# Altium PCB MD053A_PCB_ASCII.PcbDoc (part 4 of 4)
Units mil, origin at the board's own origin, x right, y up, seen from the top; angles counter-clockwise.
Board outline 3650 x 5180 mil, 4 copper layers (Top Layer, GND Layer, Power Layer, Bottom Layer), stack 58.4 mil thick; 251 components, 138 nets, 532 pads, 1017 vias.
Unrouted connection lines stored in the file: 42.
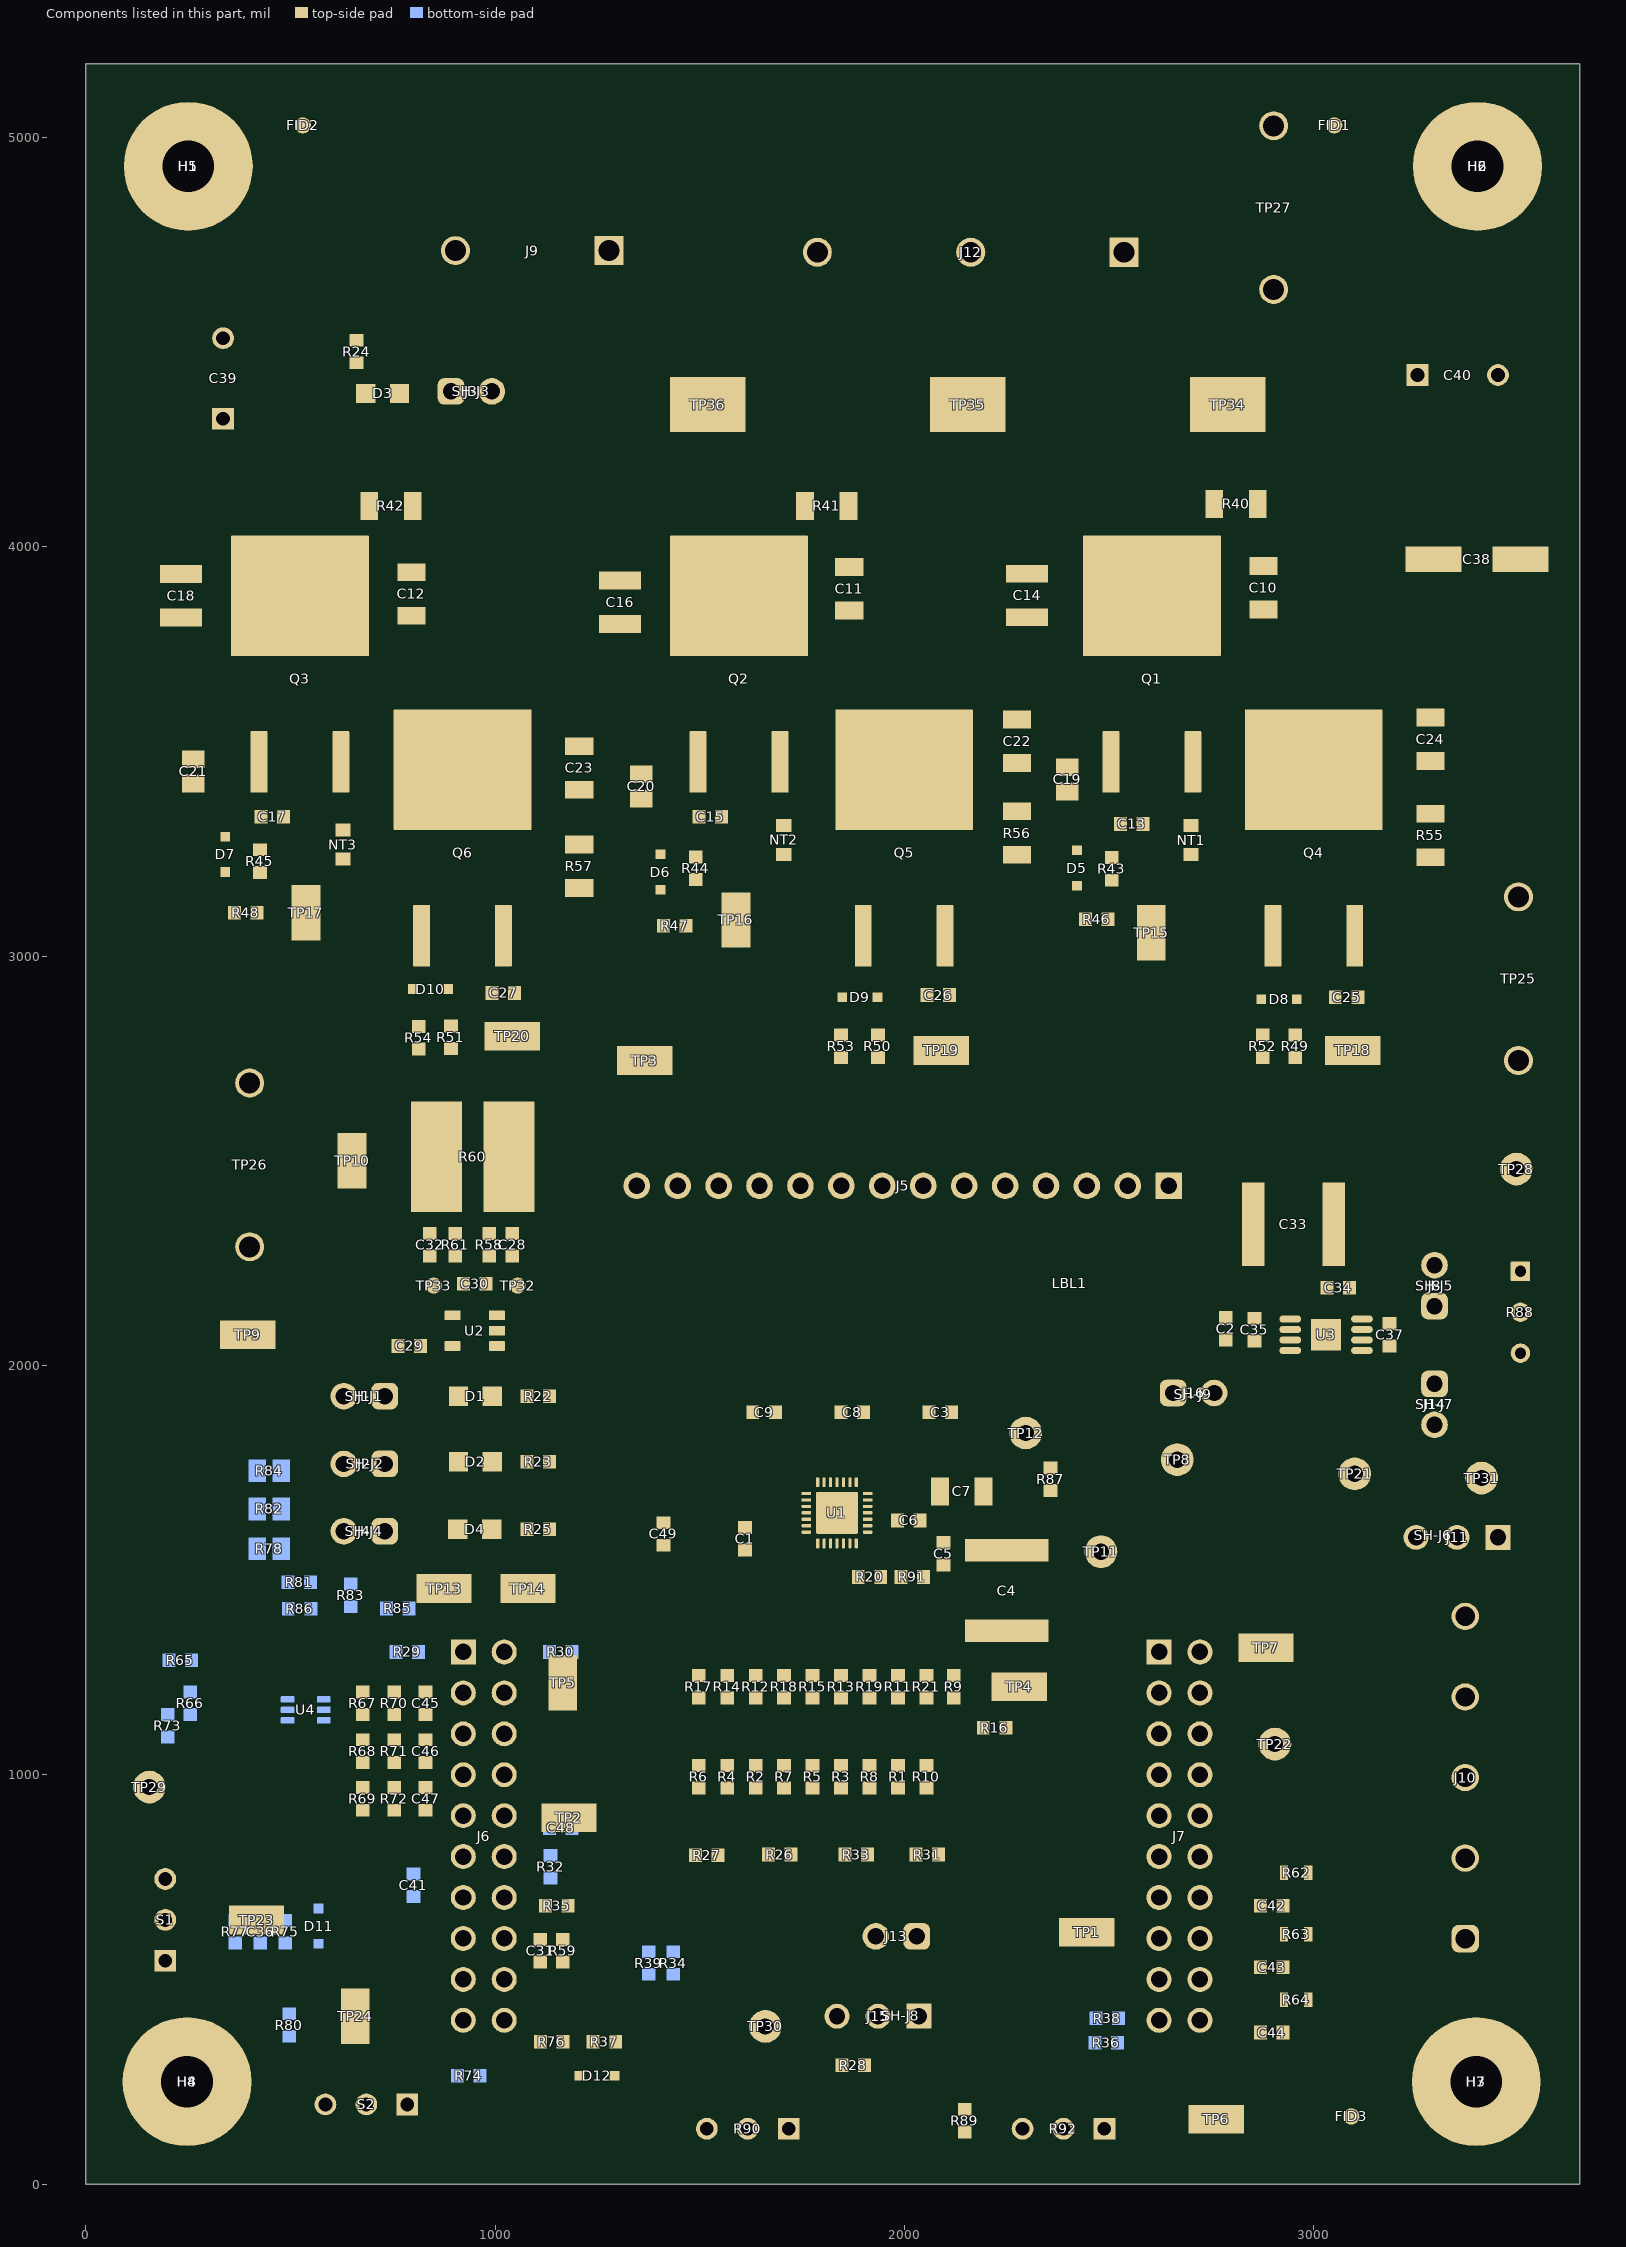
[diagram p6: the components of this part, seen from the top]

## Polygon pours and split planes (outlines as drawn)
GVDD on Top Layer "TOP_LAYER_GVDD_P124" (solid, remove dead copper, pour order 124): 2079.4,1760.22 2111.75,1760.22 2246.54,1895 2375,1895 2375,1726.8 2373.2,1725 2369.08,1729.12 2140,1729.12 2140,1655.75 1962.16,1648.98
PVDD on Top Layer "TOP_LAYER_PVDD_P128" (solid, remove dead copper, pour order 128): 3005,2515 3005,2225 3057.17,2225 3057.17,2125 3080,2125 3080,2102.56 3150,2102.56 3150,2190 3345,2190 3345,2515
GND on Top Layer "TOP_LAYER_GND_P157" (solid, remove dead copper, pour order 157): 24.84,5196.95 3674.84,5196.95 3674.84,16.95 24.84,16.95
AVDD on Top Layer "TOP_LAYER_AVDD_P145" (solid, remove dead copper, pour order 145): 1701.22,1905 1365,1905 1342.2,1882.2 1342.2,1777.53 1354.73,1765 1605.25,1765 1605.25,1830.55 1683.62,1830.55 1725.32,1872.25 1701.22,1896.35
PVDD on Top Layer "TOP_LAYER_PVDD_P144" (solid, remove dead copper, pour order 144): 2890,4565 3356.77,4565 3375,4546.77 3375,3690.23 3345,3680.72 3150,3680.72 3150,4170 2890,4430
LSS on Top Layer "TOP_LAYER_LSS_P141" (solid, remove dead copper, pour order 141): 930,3430 3331.96,3430 3405,3356.96 3405,3171.26 3310,3076.26 3310,2477.55 1412.92,2477.55 1395.1,2355 1284,2355 1240,2355 1110,2355 1090,2375 970,2375 970,2920.47 680.94,3135 680,3244.68 970,3361.8
GLA_FET on Top Layer "TOP_LAYER_GLA_FET_P139" (solid, remove dead copper, pour order 139): 2875,3130 2922.73,3130 2927.73,3125 2935.94,2950 3060.5,2940 3080,2920.5 3080,2780 2920,2780 2915,2785 2915,2919.83 2875,2959.83
GLB_FET on Top Layer "TOP_LAYER_GLB_FET_P138" (solid, remove dead copper, pour order 138): 1868.41,3132.12 1919.81,3132.12 1926.42,3125.51 1926.42,2981.32 1975.47,2932.27 2078.23,2932.27 2085,2925.5 2085,2775 2065,2755 2040,2780 1890,2780 1890,2950 1868.31,2950
GLC_FET on Top Layer "TOP_LAYER_GLC_FET_P137" (solid, remove dead copper, pour order 137): 790,3133.59 791.47,3132.12 855,3132.12 855,2990 907.42,2937.58 1024.72,2937.58 1024.72,2870.28 1067.44,2827.56 1068.11,2740 979.89,2740 850,2740 850,2915.33 815,2950.33 790,2950.33
GHA_FET on Top Layer "TOP_LAYER_GHA_FET_P136" (solid, remove dead copper, pour order 136): 2445,3561.47 2575,3561.47 2575,3377.97 2555,3357.97 2555,3251.8 2635,3171.8 2635,3035 2564.4,3035 2564.4,3168.55 2522.95,3210 2409.59,3210 2409.59,3296.92 2445,3332.33
GHB_FET on Top Layer "TOP_LAYER_GHB_FET_P135" (solid, remove dead copper, pour order 135): 1445,3563.13 1447.66,3565.78 1565,3565.78 1565,3385 1522.44,3385 1525,3382.44 1525,3284.98 1625,3184.98 1625,3052.68 1617.32,3045 1533.11,3045 1530,3048.11 1530,3216.78 1526.78,3220 1380,3220 1380,3282.42 1445,3347.42
GHC_FET on Top Layer "TOP_LAYER_GHC_FET_P134" (solid, remove dead copper, pour order 134): 350,3565.78 350,3361.95 323.38,3335.33 323.38,3237.91 459.69,3237.91 467.6,3230 467.6,3080.51 500,3048.11 572.34,3048.11 572.34,3224.36 457.72,3338.98 457.72,3565.78
GND on Top Layer "TOP_LAYER_GND_P133" (solid, remove dead copper, pour order 133): 1169,3904.41 1434.08,3904.41 1437.58,3900.91 1437.58,3575.12 1173.88,3575.12 1169,3580
GND on Top Layer "TOP_LAYER_GND_P132" (solid, remove dead copper, pour order 132): 2184.35,3914.49 2443.8,3914.49 2462.2,3896.09 2462.2,3619.49 2459.53,3622.17 2184.35,3622.17
PVDD on Top Layer "TOP_LAYER_PVDD_P131" (solid, remove dead copper, pour order 131): 2803.49,3682.2 2803.49,4136.78 2725.26,4215 2291.73,4215 2291.73,4103.85 2244.09,4056.21 2235,4056.21 2235,3919.41 2250,3904.41 2422.56,3904.41 2435.08,3891.89 2435.08,3622.17 2350,3537.09 2350,3446.49 2360.98,3435.51 2437.68,3435.51 2450,3447.83 2450,3537.09 2564.4,3580 2592.91,3680 2602.4,3680
PVDD on Top Layer "TOP_LAYER_PVDD_P130" (solid, remove dead copper, pour order 130): 1775.57,3655 1775.57,4023.9 1806.68,4055 1803.68,4058 1801.38,4058 1801.38,4132.76 1848.62,4180 1893.74,4180 1892.29,4215 1489.15,4215 1341.24,4055 1287.6,4055 1225,3992.4 1225,3880.2 1400.43,3880.2 1411.06,3869.57 1411.06,3665.2 1411.06,3647.14 1382.58,3574.19 1300,3517.09 1300,3411.65 1421.26,3415.15 1559.71,3655
PVDD on Top Layer "TOP_LAYER_PVDD_P129" (solid, remove dead copper, pour order 129): 710.13,4006.54 747.36,4043.77 747.36,4170.44 1015.44,4170.44 1450,4605 1450,4842.44 1412.44,4880 1174.2,4880 1124.2,4830 1124.2,4829.2 1100,4805 1100,4700 855,4455 611,4455 561,4426.57 539.43,4426.57 301.85,4426.57 150.67,4275.39 150.67,3905 313.11,3905 313.11,3652.43 207.48,3585.59 207.48,3467.91 325.15,3467.91 653.18,3652.43 710.13,3709.38
OUTA on Top Layer "TOP_LAYER_OUTA_P127" (solid, remove dead copper, pour order 127): 2762.91,3283.5 2560,3283.5 2560,3376.97 2602.4,3419.37 2602.4,3645.17 2612.46,3655.23 2816.93,3655.23 2816.93,3891.89 2830.04,3905 2917.56,3905 2917.56,4145.16 2882.72,4180 2787.91,4180 2758.75,4218.66 2626.5,4218.66 2381.1,4489.1 2381.1,4880 2656.8,4880 2760.94,4775.85 2760.94,4614.69 3175,4200.63 3175,3682.2 3224.2,3633 3375,3633 3375,3555 3350,3530 3199.98,3530 3199.98,3234.88 3170.1,3205 2762.91,3205
OUTB on Top Layer "TOP_LAYER_OUTB_P126" (solid, remove dead copper, pour order 126): 1550,3292.2 1535,3292.2 1535,3367.94 1556.8,3377.42 1556.8,3619.49 1806.68,3619.49 1806.68,3878.8 1832.87,3905 1929.13,3905 1890.66,4230.2 1680,4230.2 1899.05,4455 1982.81,4538.76 1988.23,4880 2315,4880 2365,4880 2365,4488.16 2615.89,4220 2319.31,4220 2315,4156.04 2211.32,4052.36 2211.32,3649.5 2325,3649.5 2322.64,3647.14 2322.64,3519.49 2201.02,3519.49 2201.02,3263.6 2156.8,3219.37 1778.58,3219.37 1778.58,3283.5 1769.88,3292.2 1561.52,3292.2 1556.8,3292.2
OUTC on Top Layer "TOP_LAYER_OUTC_P125" (solid, remove dead copper, pour order 125): 465.1,3540.65 579.45,3655 747.36,3655 747.36,3869.57 736.93,3880 868.48,3880.2 868.48,4155 1006.9,4161.5 1745.5,4880 1960.31,4880 1964.76,4634.76 1964.76,4505 1690,4229.32 1575,4229.32 1410,4080 1275,4080 1200,4005 1200,3630 1265.99,3564.01 1265.99,3467.91 1137.91,3467.91 1121.97,3451.97 1121.97,3255 703.72,3255 683.31,3275.42 519.33,3275.42 465.1,3329.65
LSS on Power Layer "POWER_LAYER_LSS_P140" (solid, remove dead copper, pour order 140): 930,3430 3331.96,3430 3405,3356.96 3405,3171.26 3310,3076.26 3310,2477.55 1412.92,2477.55 1395.1,2355 1284,2355 1240,2355 1110,2355 1090,2375 970,2375 970,2920.47 680.94,3135 680,3244.68 970,3361.8
GND on Power Layer "POWER_LAYER_GND_P165" (solid, remove dead copper, pour order 165): 0,5180 3650,5180 3650,0 0,0
AVDD on Power Layer "POWER_LAYER_AVDD_P153" (solid, remove dead copper, pour order 153): 1702.02,1904.76 1365.8,1904.76 1343,1881.96 1343,1777.29 1355.53,1764.76 1565,1764.76 1635,1830.31 1684.42,1830.31 1726.12,1872.01 1702.02,1896.11
PVDD on Power Layer "POWER_LAYER_PVDD_P149" (solid, remove dead copper, pour order 149): 1412.44,4880 1450,4842.44 1450,4628.1 1051.9,4230 3192,4230 2890,4521.68 2890,4565 3385.61,4565 3387.09,4563.52 3386,4218 3386,3275.5 3277.16,3166.66 416.21,3166.66 313.11,3269.76 313.11,3905 150.67,3905 150.67,4275.39 301.85,4426.57 561,4426.57 589.42,4455 855,4455 1100,4700 1100,4805.8 1174.2,4880
OUTA on Power Layer "POWER_LAYER_OUTA_P148" (solid, remove dead copper, pour order 148): 3174.36,4185 2786.28,4185 2757.11,4223.66 2624.86,4223.66 2379.47,4494.1 2379.47,4885 2655.16,4885 2759.31,4780.85 2759.31,4619.69 3174.36,4227.33
OUTB on Power Layer "POWER_LAYER_OUTB_P147" (solid, remove dead copper, pour order 147): 2319,4230.2 1680,4230.2 1899.05,4455 1982.81,4538.76 1988.23,4880 2315,4880 2365,4880 2365,4488.16 2604,4230.2
OUTC on Power Layer "POWER_LAYER_OUTC_P146" (solid, remove dead copper, pour order 146): 1077.62,4231.84 1746.12,4881.84 1965.38,4880 1965.38,4636.6 1965.38,4506.84 1690.62,4231.16
LSS on GND Layer "GND_LAYER_LSS_P158" (solid, remove dead copper, pour order 158): 930,3430 3331.96,3430 3405,3356.96 3405,3171.26 3310,3076.26 3310,2477.55 1412.92,2477.55 1395.1,2355 1284,2355 1240,2355 1110,2355 1090,2375 970,2375 970,2920.47 680.94,3135 680,3244.68 970,3361.8
GND on GND Layer "GND_LAYER_GND_P159" (solid, remove dead copper, pour order 159): 0,5180 3650,5180 3650,0 0,0
OUTA on GND Layer "GND_LAYER_OUTA_P152" (solid, remove dead copper, pour order 152): 3208.31,4184.48 2800.59,4184.48 2771.43,4223.14 2639.17,4223.14 2393.78,4493.58 2393.78,4884.48 2669.47,4884.48 2773.62,4780.33 2773.62,4619.17
OUTB on GND Layer "GND_LAYER_OUTB_P151" (solid, remove dead copper, pour order 151): 2319,4230.2 1680,4230.2 1899.05,4455 1982.81,4538.76 1988.23,4880 2315,4880 2365,4880 2365,4488.16 2604,4230.2
OUTC on GND Layer "GND_LAYER_OUTC_P150" (solid, remove dead copper, pour order 150): 1081.11,4231.82 1749.61,4881.82 1968.87,4879.99 1968.87,4636.59 1968.87,4506.82 1694.11,4231.15
LSS on Bottom Layer "BOTTOM_LAYER_LSS_P143" (solid, remove dead copper, pour order 143): 930,3430 3331.96,3430 3405,3356.96 3405,3171.26 3310,3076.26 3310,2477.55 1412.92,2477.55 1395.1,2355 1284,2355 1240,2355 1110,2355 1090,2375 970,2375 970,2920.47 680.94,3135 680,3244.68 970,3361.8
OUTA on Bottom Layer "BOTTOM_LAYER_OUTA_P156" (solid, remove dead copper, pour order 156): 3208.31,4180 2800.59,4180 2771.43,4218.66 2639.17,4218.66 2393.78,4489.1 2393.78,4880 2669.47,4880 2773.62,4775.85 2773.62,4614.69
OUTB on Bottom Layer "BOTTOM_LAYER_OUTB_P155" (solid, remove dead copper, pour order 155): 2325,4225 1686,4225 1905.06,4449.8 1988.81,4533.55 1994.23,4874.8 2321,4874.8 2371,4874.8 2371,4482.95 2610,4225
OUTC on Bottom Layer "BOTTOM_LAYER_OUTC_P154" (solid, remove dead copper, pour order 154): 1081.11,4231.82 1749.61,4881.82 1968.87,4879.99 1968.87,4636.59 1968.87,4506.82 1694.11,4231.15
GND on Bottom Layer "BOTTOM_LAYER_GND_P167" (solid, remove dead copper, pour order 167): 0,5180 3650,5180 3650,0 0,0

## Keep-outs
Keep-Out Layer:
  text ".Layer_Name" at 577,-428.49 h60

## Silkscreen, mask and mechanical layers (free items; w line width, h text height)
Top Overlay:
  lines w8: 314,776 330,792 ; 316,472 334,454 ; 330,733 330,792 ; 334,513 334,454 ; 346,776 330,792 ; 351,471 334,454 ; 515,380 495,360 ; 516,339 495,360 ; 571,360 495,360 ; 747,369 819,369 800,388 ; 800,352 818,370
  lines w10: 1462.65,1060 2090,1060 2090,1270 ; 2204,1596 2205,1595 ; 2204,1596 2205,1595 ; 2204,1596 2204,1925 1570,1925 1570,1456.48 2120.5,1456.48 2120.5,1310 2371.66,1310 2371.66,1595 2355,1595 2205,1595 ; 1462.65,850 1462.65,1270 2155,1270 2155,850 1462.65,850
  text "GND" at 833.69,4455 h40
  text "PVDD" at 1200,4455 h40
  text "OUTC" at 1711.59,4454.45 h40
  text "OUTB" at 2084.79,4454.45 h40
  text "OUTA" at 2458,4454.45 h40
  text "LSS" at 1344.97,2511.91 h30 r45
  text "GLC" at 1438.97,2509.91 h30 r45
  text "SHC" at 1638.97,2506.91 h30 r45
  text "GHC" at 1536.97,2503.91 h30 r45
  text "BSTC" at 1744.97,2503.91 h30 r45
  text "GLB" at 1857.97,2503.91 h30 r45
  text "GHB" at 1952.97,2503.91 h30 r45
  text "SHB" at 2053.97,2503.91 h30 r45
  text "BSTB" at 2149.97,2503.91 h30 r45
  text "GLA" at 2258.97,2503.91 h30 r45
  text "GHA" at 2368.97,2503.91 h30 r45
  text "SHA" at 2469.97,2503.91 h30 r45
  text "BSTA" at 2562.97,2503.91 h30 r45
  text "GND" at 2669.97,2503.91 h30 r45
  text "LDO_" at 3235,2365 h30
  text "EN" at 3256.86,2320 h30
  text "DRV8328A/B/C/D" at 1648.36,1945 h35
  text "AVDD" at 445,1889.57 h30
  text "DT" at 3479.33,1875.99 h30
  text "DT_POT" at 3042.76,1870 h30
  text "EXT_" at 3475,1765 h30
  text "HALL_" at 3175,1735 h30
  text "nFAULT" at 382.01,1726 h30
  text "HALL_" at 3475,1720 h30
  text "PWR" at 3175,1695 h30
  text "PWR" at 3475,1677.56 h30
  text "HALL_PWR_" at 2829.03,1605 h30
  text "MCU_LED" at 342.73,1560.1 h30
  text "SEL" at 3010,1545 h30
  text "EXT" at 3560,1540 h30 r90
  text "AVDD" at 3172.2,1525 h30 r90
  text "AVDD cap" at 1311.03,1496.81 h25
  text "(for C/D)" at 1308.48,1457.2 h25
  text "HALL" at 2997.79,1420 h35
  text "A/B" at 1874.37,1415 h30
  text "DT" at 1993.06,1370 h30
  text "PWR" at 3032.2,1365 h35
  text "HALLA" at 2961.09,1180 h35
  text "DRV8328AEVM" at 173.27,1121.81 h120 r90
  text "A/B" at 1435,1120 h30 r90
  text "'.PRJ_Number'.PCB_Rev" at 291.7,1111.24 h108.27 r90
  text "HALLB" at 2966.09,977.2 h35
  text "C/D" at 1430,920 h30 r90
  text "HALLC" at 2966.54,796.3 h35
  text "SLEEP" at 396.2,735 h30 r90
  text "VDS_DIS" at 1879.36,673.51 h30
  text "GND" at 3030.31,535 h35
  text "DRV" at 733,442 h30
  text "DRV" at 497,440 h30
  text "WAKE" at 403.97,430 h30 r90
  text "VDS_EXT" at 1395,400.99 h30
  text "OFF" at 496,396 h30
  text "ON" at 734,396 h30
  text "POT" at 2143.46,370.67 h30 r90
  text "EXT" at 1764.15,367.64 h30 r90
  text "VDSLVL" at 2302.65,255.57 h30
  text ".Layer_Name" at 577,-428.49 h60
Bottom Overlay:
  text ".Layer_Name" at 577,-428.49 h60
Top Paste:
  text ".Layer_Name" at 577,-428.49 h60
Bottom Paste:
  text ".Layer_Name" at 577,-428.49 h60
Top Solder:
  text ".Layer_Name" at 577,-428.49 h60
  text ".Layer_Name" at 577,-428.49 h60
Solder Side:
  text ".Layer_Name" at 577,-428.49 h60
Drill Guide:
  text ".Layer_Name" at 577,-428.49 h60
M1 Board Outline:
  the board outline again, w10
  text ".Layer_Name" at 577,-428.49 h60
M2 Board Dimensions:
  rectangle: 0,155 125,280
  rectangle: 125,30 500,155
  lines w7: 0,155 1000,155 ; 125,30 125,280 ; 250,30 250,280 ; 500,30 500,280 ; 750,30 750,280 ; 0,30 1000,30 1000,280 0,280 0,30
  text ".Layer_Name" at 577,-428.49 h60
M3 3D STEP Top:
  text ".Layer_Name" at 577,-428.49 h60
M4 3D STEP Bottom:
  text ".Layer_Name" at 577,-428.49 h60
M5 Assembly Top:
  lines w10: -292,-500.17 6308,-500.17 ; -292,-296.83 6310,-296.83 ; -292,-93.5 -292,-703.5 3713,-703.5 6310,-703.5 6310,-93.5 -291.5,-93.5 -291.5,-703.5 1284,-703.5 ; 2173,-703.5 2173,-93.5 ; 3440,-296.83 3440,-93.5 ; 4280,-296.83 4280,-93.5 ; 4902,-710 4902,-507.17
  text "COMPONENTS MARKED 'DNP' SHOULD NOT BE POPULATED." at 1153.5,111.5 h60
  text "ASSEMBLY VARIANT:" at 1153,-4 h60
  text ".VariantName" at 2189,-4 h60
  text "PCB VIEWED FROM TOP SIDE" at -228.5,-225.67 h60
  text "BOARD #:" at 2248,-225.67 h60
  text ".PRJ_Number" at 2793.5,-225.67 h60
  text "REV:" at 3638,-225.67 h60
  text ".PCB_Rev" at 3929.5,-225.67 h60
  text "SVN REV:" at 4476,-225.67 h60
  text ".VersionControl_RevNumber" at 4982,-225.67 h60
  text "TID #:" at 2248,-429 h60
  text ".TID" at 2793.5,-429 h60
  text "PLOT NAME =" at -228.5,-634.34 h60
  text ".plot_File_Name" at 577,-634.34 h60
  text "GENERATED    :" at 2250,-634.34 h60
  text ".Print_Date" at 3119.5,-634.34 h60
  text ".Print_Time" at 3848.5,-634.34 h60
  text "TEXAS INSTRUMENTS" at 5113,-634.34 h60
M6 Assembly Bottom:
  lines w10: -292.5,-297.33 6309.5,-297.33 ; -290.5,-500.67 6309.5,-500.67 ; 1115.5,-710.5 1115.5,-507.67 ; 1737.5,-297.33 1737.5,-94 ; 2577.5,-297.33 2577.5,-94 ; 3844.5,-704 3844.5,-94 ; 4733.5,-704 6309,-704 6309,-94 -292.5,-94 -292.5,-704 2304.5,-704 6309.5,-704 6309.5,-94
  text "COMPONENTS MARKED 'DNP' SHOULD NOT BE POPULATED." at 6102,112 h60
  text ".VariantName" at 5058,-4 h60
  text "ASSEMBLY VARIANT:" at 6097,-4 h60
  text ".VersionControl_RevNumber" at 1035.5,-226.17 h60
  text "SVN REV:" at 1541.5,-226.17 h60
  text ".PCB_Rev" at 2088,-226.17 h60
  text "REV:" at 2379.5,-226.17 h60
  text ".PRJ_Number" at 3224,-226.17 h60
  text "BOARD #:" at 3769.5,-226.17 h60
  text "PCB VIEWED FROM BOTTOM SIDE" at 6246,-226.17 h60
  text ".TID" at 3224,-429.5 h60
  text "TID #:" at 3769.5,-429.5 h60
  text "TEXAS INSTRUMENTS" at 904.5,-634.84 h60
  text ".Print_Time" at 2169,-634.84 h60
  text ".Print_Date" at 2898,-634.84 h60
  text "GENERATED    :" at 3767.5,-634.84 h60
  text ".plot_File_Name" at 5440.5,-634.84 h60
  text "PLOT NAME =" at 6246,-634.84 h60
M9 Title Sheet:
  lines w10: -491.5,1471.5 -291.5,1471.5 ; -491.5,3846.5 -291.5,3846.5 ; -491.5,6221.5 -291.5,6221.5 ; 2008.5,-903.5 2008.5,-703.5 ; 2008.5,8396.5 2008.5,8596.5 ; 4508.5,-903.5 4508.5,-703.5 ; 4508.5,8396.5 4508.5,8596.5 ; 6321,-703.5 6321,-93.5 11303.5,-93.5 ; 7008.5,-903.5 7008.5,-703.5 ; 7008.5,8396.5 7008.5,8596.5 ; 9508.5,-903.5 9508.5,-703.5 ; 9508.5,8396.5 9508.5,8596.5 ; 11303.5,-703.5 11303.5,-93.5 ; 11303.5,-393.5 14303.5,-393.5 ; 11303.5,206.5 14303.5,206.5 ; 11304.5,800.5 14304.5,800.5 ; 12008.5,-903.5 12008.5,-703.5 ; 12008.5,8396.5 12008.5,8596.5 ; 12808.5,-693.5 12808.5,-93.5 ; 14303.5,-93.5 11303.5,-93.5 ; 14303.5,506.5 11303.5,506.5 ; 14308.5,496.5 14308.5,-703.5 ; 14308.5,1301 11304.5,1301 11303.5,1301 11303.5,800.5 11303.5,506.5 ; 14308.5,1471.5 14508.5,1471.5 ; 14308.5,3846.5 14508.5,3846.5 ; 14308.5,6221.5 14508.5,6221.5 ; 11303.5,-93.5 11303.5,506.5 ; 14308.5,-703.5 14308.5,8396.5 -291.5,8396.5 -291.5,-703.5 14308.5,-703.5 ; -491.5,-903.5 -491.5,8596.5 14508.5,8596.5 14508.5,-903.5 -491.5,-903.5
  text "1" at 739.84,8466.5 h70
  text "2" at 3235.5,8466.5 h70
  text "3" at 5724.84,8466.5 h70
  text "4" at 8231.51,8466.5 h70
  text "5" at 10730.5,8466.5 h70
  text "6" at 13235.5,8466.5 h70
  text "A" at -416.5,7323.5 h70
  text "A" at 14383.5,7323.5 h70
  text "B" at -416.5,4943.5 h70
  text "B" at 14383.5,4943.5 h70
  text "C" at -416.5,2568.5 h70
  text "C" at 14383.5,2568.5 h70
  text "PROJECT TITLE:" at 11343.5,707.5 h45
  text ".PRJ_Title" at 11393.5,574.17 h70
  text "DESIGNED FOR:" at 11343.5,406.5 h45
  text ".PRJ_Customer" at 11393.5,266.5 h70
  text "D" at -416.5,198.5 h70
  text "D" at 14383.5,198.5 h70
  text "FILE NAME:" at 11343.5,106.5 h45
  text ".PCB_File_Name_No_Path" at 11393.5,-13.5 h70
  text "Texas Instruments (TI) and/or its licensors do not warrant the accuracy or completeness of this specification" at 6374,-175.34 h45
  text "ENGINEER:" at 11343.5,-183.5 h45
  text "LAYOUT BY:" at 12848.5,-183.5 h45
  text "or any information contained therein. TI and/or its licensors do not warrant that this design will meet" at 6329.01,-288 h45
  text ".PRJ_Engineer" at 11393.5,-338.49 h70
  text ".PCB_Layout" at 12899,-338.49 h70
  text "the specifications, will be suitable for your application or fit for any particular purpose, or will operate in" at 6329.01,-400.67 h45
  text ".Layer_Name" at 577,-428.49 h60
  text "ALTIUM DESIGNER VERSION:" at 12848.5,-493.5 h45
  text "an implementation. TI and/or its licensors do not warrant that the design is production worthy. You should" at 6329.01,-513.33 h45
  text "completely validate and test your design implementation to confirm the system functionality for your application." at 6374,-626 h45
  text ".print_Scale" at 11393.5,-626.83 h70
  text ".Application_BuildNumber" at 12899,-626.83 h70
  text "1" at 739.84,-833.5 h70
  text "2" at 3235.5,-833.5 h70
  text "3" at 5724.84,-833.5 h70
  text "4" at 8231.51,-833.5 h70
  text "5" at 10730.5,-833.5 h70
  text "6" at 13235.5,-833.5 h70
M10 Fab Notes:
  drawing of 189 lines, arcs and shapes, not listed
  text "DESIGN INFORMATION" at 12382.02,6786.17 h60
  text "MIN. TRACK WIDTH:" at 11737.46,6654.05 h60
  text "8" at 12833.7,6654.05 h60
  text "MIL" at 12988.46,6654.05 h60
  text "MIN. CLEARANCE:" at 11737.46,6529.92 h60
  text "0.2" at 12773.7,6529.93 h60
  text "mm" at 12988.46,6529.92 h60
  text "MIN. VIA PAD SIZE:" at 11737.46,6405.8 h60
  text "24" at 12803.71,6405.8 h60
  text "MIL" at 12988.46,6405.8 h60
  text "0.05mm (2MIL)" at 12432.46,6275.9 h60
  text "MINIMUM ANNULAR RING" at 11408.23,6267.67 h60
  text "EXTERNAL" at 13140.46,6267.67 h60
  text "PER" at 11608.23,6157.55 h60
  text "IPC-D-275 CLASS 2 LEVEL C" at 11828.23,6157.54 h60
  text "MIL, HOLES" at 13316.46,6057.07 h60
  text "+/-" at 12924,6048.48 h60
  text "+/-" at 13778,6048.48 h60
  text "REGISTRATION TOLERANCES:" at 11408.23,6047.42 h60
  text "METAL" at 12608,6047.42 h60
  text "5" at 13184.2,6047.42 h60
  text "3" at 14017.2,6047.42 h60
  text "MIL" at 14133.46,6047.42 h60
  text "HOLE SIZE TOLERANCE (UNLESS OTHERWISE SPECIFIED):" at 11408.23,5949.1 h60
  text "+/-" at 13778,5946.23 h60
  text "3" at 14017.2,5945.17 h60
  text "MIL" at 14133.46,5945.17 h60
  text "MATERIAL:" at 11333.46,5807.52 h60
  text "FR-4 High Tg" at 12319.9,5679 h60
  text "X" at 12175.46,5671.01 h60
  text "FR-408" at 11754.46,5666.49 h60
  text "OTHER" at 13242.46,5666.49 h60
  text "62 MIL (1.6mm) +/-10%" at 12074.56,5523.46 h60
  text "X" at 11954.46,5521.01 h60
  text "THICKNESS:" at 11408.23,5515.24 h60
  text "OTHER" at 13359.46,5515.24 h60
  text "TOLERANCE:" at 11408.23,5376.92 h60
  text "X" at 12256.46,5376.92 h60
  text "ANSI IPC-6012 TYPE 3 CLASS 2" at 12434.48,5376.92 h60
  text "OTHER +/-" at 12434.46,5232.73 h60
  text "BOW & TWIST:" at 11408.23,5087.54 h60
  text "X" at 12256.46,5087.54 h60
  text "ANSI IPC-6012 TYPE 3 CLASS 2" at 12434.48,5087.54 h60
  text "OTHER +/-" at 12434.46,4940.85 h60
  text "DRILLING:" at 11333.46,4810.23 h60
  text "NC_DRILL FILES" at 13094.46,4705.04 h60
  text "REFERENCE:" at 11408.23,4701.1 h60
  text "X" at 12065.46,4701.01 h60
  text "AS SHOWN" at 12243.46,4701.1 h60
  text "X" at 12966.46,4701.1 h60
  text "OTHER" at 13392.46,4558.85 h60
  text "PTH COPPER THICKNESS:" at 11407.91,4555.32 h60
  text "X" at 12547.14,4555.32 h60
  text "20-30 um" at 12675.14,4555.32 h60
  text "BOARD FINISH:" at 11333.46,4407.73 h60
  text "SILKSCREEN:" at 11488.68,4297.6 h60
  text "X" at 12446.46,4297.6 h60
  text "TOP" at 12563.46,4297.6 h60
  text "X" at 12956.46,4297.6 h60
  text "BOTTOM" at 13074.46,4297.6 h60
  text "SILKSCREEN COLOR:" at 11488.68,4142.41 h60
  text "X" at 12445.46,4142.41 h60
  text "WHITE" at 12563.46,4142.41 h60
  text "OTHER" at 13074.46,4142.41 h60
  text "X" at 12576.46,3998.96 h60
  text "GREEN" at 12694.46,3998.96 h60
  text "OTHER" at 13312.46,3998.96 h60
  text "SOLDER RESIST COLOR:" at 11488.68,3992.1 h60
  text "X" at 12576.46,3844.71 h60
  text "MATTE" at 12694.46,3844.71 h60
  text "SEMI-GLOSS" at 13312,3844.07 h60
  text "IMMERSION GOLD (ENIG)" at 12394.46,3671.94 h60
  text "ENEPIG" at 13732,3664.72 h60
  text "SURFACE FINISH:" at 11333.46,3663.72 h60
  text "X" at 12216.46,3663.72 h60
  text "IMM. TIN/SILVER OR EQUIV" at 11663,3526.4 h60
  text "OTHER" at 13094.46,3522.47 h60
  text "ARRAY/PANEL:" at 11333.46,3367.09 h60
  text "CUT AND TRIM PER M1 BOARD OUTLINE" at 12394.46,3358.87 h60
  text "N.C. ROUTE" at 12394.46,3222.9 h60
  text "X" at 13082.46,3222.9 h60
  text "V. SCORE" at 13260.46,3222.9 h60
  text "CERTIFICATION:" at 11333.46,3093.77 h60
  text "MATERIALS AND WORKMANSHIP FOR ALL PCBS" at 12058.46,3093.77 h60
  text "TO MEET OR EXCEED THE REQUIREMENTS OF:" at 12058.46,2999.71 h60
  text "X" at 11695.97,2871.08 h60
  text "ANSI IPC-A-600F CLASS ->" at 11823.96,2871.08 h60
  text "X" at 13471.97,2871.08 h60
  text "2" at 13581.96,2871.08 h60
  text "1" at 13266.96,2869.58 h60
  text "3" at 13935.96,2869.58 h60
  text "X" at 12507.97,2723.39 h60
  text "RoHS" at 12635.96,2723.39 h60
  text "OTHER" at 13280.36,2723.39 h60
  text "PER ORDER" at 13677.42,2723.39 h60
  text "ALL BOARDS MUST MEET OR EXCEED UL94-V0 REQUIREMENTS." at 11361,2569.57 h60
  text "PCB MUST BEAR THE UL94V-0 UL REGISTERED MATERIAL ID NUMBER" at 11361,2453.5 h60
  text "ADDITIONAL REQUIREMENTS:" at 11333.46,2284.08 h60
  text "MICROSECTION:" at 11408.23,2176.95 h60
  text "YES" at 12313.96,2176.95 h60
  text "REQUIRED" at 13175.46,2032.62 h60
  text "BARE BOARD ELEC. TEST:" at 11408.23,2029.76 h60
  text "NONE" at 12713.96,2029.76 h60
  text "X" at 13057.46,2029.76 h60
  text "PER ORDER" at 13767.46,2029.76 h60
  text "XX MIL VIAS REQUIRE NON-CONDUCTIVE FILL AND PLANARIZE" at 11576.38,1824.82 h59
  text "XX MIL VIAS REQUIRE CONDUCTIVE FILL AND PLANARIZE" at 11584.38,1720.84 h60
  text "OUTER XX MIL TRACES REQUIRE 50 OHM SINGLE-ENDED IMPEDANCE" at 11583.39,1557.46 h58
  text "LAYER 2 & 3 (INNER LAYERS) XX MIL WIDE, XX MIL SPACE / TRACES REQUIRE 100 OHM DIFFERENTIAL IMPEDANCE" at 11575.39,1321.74 h60
  text ".Layer_Name" at 577,-428.49 h60
M11 Gerber Information:
  lines w10: -292,-500.17 6308,-500.17 ; -292,-296.83 6310,-296.83 ; -292,-93.5 -292,-703.5 3713,-703.5 6310,-703.5 6310,-93.5 -291.5,-93.5 -291.5,-703.5 1284,-703.5 ; 2173,-703.5 2173,-93.5 ; 3440,-296.83 3440,-93.5 ; 4280,-296.83 4280,-93.5 ; 4902,-710 4902,-507.17
  text "ALL ARTWORK VIEWED FROM TOP SIDE" at -228.5,-225.67 h60
  text "BOARD #:" at 2248,-225.67 h60
  text ".PRJ_Number" at 2793.5,-225.67 h60
  text "REV:" at 3638,-225.67 h60
  text ".PCB_Rev" at 3929.5,-225.67 h60
  text "SVN REV:" at 4476,-225.67 h60
  text ".VersionControl_RevNumber" at 4982,-225.67 h60
  text "LAYER NAME =" at -228.5,-428.49 h60
  text "TID #:" at 2248,-429 h60
  text ".TID" at 2793.5,-429 h60
  text "PLOT NAME =" at -228.5,-634.34 h60
  text ".plot_File_Name" at 577,-634.34 h60
  text "GENERATED    :" at 2250,-634.34 h60
  text ".Print_Date" at 3119.5,-634.34 h60
  text ".Print_Time" at 3848.5,-634.34 h60
  text "TEXAS INSTRUMENTS" at 5113,-634.34 h60
M12 Stackup:
  drawing of 295 lines, arcs and shapes, not listed
  text "Layer" at 6509.09,7478.5 h60
  text "Name" at 6919,7478.5 h60
  text "Material" at 7848.74,7478.5 h60
  text "Thickness" at 8708.51,7478.5 h60
  text "Constant" at 9358.35,7478.5 h60
  text "Board Layer Stack" at 9928.21,7478.5 h60
  text "1" at 6509.09,7358.5 h60
  text "Top Overlay" at 6919,7358.5 h60
  text "2" at 6509.09,7238.5 h60
  text "Top Solder" at 6919,7238.5 h60
  text "Solder Resist" at 7848.74,7238.5 h60
  text "0.40mil" at 8708.51,7238.5 h60
  text "3.5" at 9358.35,7238.5 h60
  text "3" at 6509.09,7118.5 h60
  text "Top Layer" at 6919,7118.5 h60
  text "Copper" at 7848.74,7118.5 h60
  text "2.80mil" at 8708.51,7118.5 h60
  text "4" at 6509.09,6998.5 h60
  text "Dielectric 2" at 6919,6998.5 h60
  text "FR-4" at 7848.74,6998.5 h60
  text "10.00mil" at 8708.51,6998.5 h60
  text "4.8" at 9358.35,6998.5 h60
  text "5" at 6509.09,6878.5 h60
  text "GND Layer" at 6919,6878.5 h60
  text "Copper" at 7848.74,6878.5 h60
  text "1.40mil" at 8708.51,6878.5 h60
  text "6" at 6509.09,6758.5 h60
  text "Dielectric 1" at 6919,6758.5 h60
  text "FR-4" at 7848.74,6758.5 h60
  text "30.00mil" at 8708.51,6758.5 h60
  text "4.2" at 9358.35,6758.5 h60
  text "7" at 6509.09,6638.5 h60
  text "Power Layer" at 6919,6638.5 h60
  text "Copper" at 7848.74,6638.5 h60
  text "1.40mil" at 8708.51,6638.5 h60
  text "8" at 6509.09,6518.5 h60
  text "Dielectric 3" at 6919,6518.5 h60
  text "FR-4" at 7848.74,6518.5 h60
  text "10.00mil" at 8708.51,6518.5 h60
  text "4.8" at 9358.35,6518.5 h60
  text "9" at 6509.09,6398.5 h60
  text "Bottom Layer" at 6919,6398.5 h60
  text "Copper" at 7848.74,6398.5 h60
  text "2.80mil" at 8708.51,6398.5 h60
  text "10" at 6509.09,6278.5 h60
  text "Solder Side" at 6919,6278.5 h60
  text "Solder Resist" at 7848.74,6278.5 h60
  text "0.40mil" at 8708.51,6278.5 h60
  text "3.5" at 9358.35,6278.5 h60
  text "11" at 6509.09,6158.5 h60
  text "Bottom Overlay" at 6919,6158.5 h60
  text ".Layer_Name" at 577,-428.49 h60
M13 Component Bodies Top:
  text ".Layer_Name" at 577,-428.49 h60
M14 Component Bodies Bottom:
  text ".Layer_Name" at 577,-428.49 h60
M15 Courtyards Top:
  text ".Layer_Name" at 577,-428.49 h60
M16 Courtyards Bottom:
  text ".Layer_Name" at 577,-428.49 h60
Drill Drawing:
  circle w10: c5363.72,3865.96 r16.58
  circle w10: c5363.72,3865.96 r27.63
  circle w10: c5363.72,2871.4 r27.63
  lines w10: 5336.09,2968.09 5391.34,2968.09 5391.34,3023.35 5336.09,3023.35 5336.09,2968.09 ; 5336.09,3147.67 5391.34,3147.67 5363.72,3092.41 5336.09,3147.67 ; 5336.09,3216.73 5363.72,3230.55 5391.34,3216.73 5377.53,3244.36 5391.34,3271.99 5363.72,3258.17 5336.09,3271.99 5349.9,3244.36 5336.09,3216.73 ; 5336.09,3354.87 5349.9,3354.87 5349.9,3341.05 5377.53,3341.05 5377.53,3354.87 5391.34,3354.87 5391.34,3382.49 5377.53,3382.49 5377.53,3396.31 5349.9,3396.31 5349.9,3382.49 5336.09,3382.49 5336.09,3354.87 ; 5336.09,3479.19 5349.9,3479.19 5363.72,3465.37 5377.53,3479.19 5391.34,3479.19 5377.53,3493 5391.34,3506.81 5377.53,3506.81 5363.72,3520.63 5349.9,3506.81 5336.09,3506.81 5349.9,3493 5336.09,3479.19 ; 5336.09,3617.32 5363.72,3589.69 5391.34,3617.32 5363.72,3644.95 5336.09,3617.32 ; 5336.09,3714.01 5391.34,3714.01 5391.34,3769.27 5336.09,3769.27 5336.09,3714.01 ; 5336.09,3962.65 5336.09,3976.47 5349.9,3990.28 5336.09,4004.09 5336.09,4017.91 5349.9,4017.91 5363.72,4004.09 5377.53,4017.91 5391.34,4017.91 5391.34,4004.09 5377.53,3990.28 5391.34,3976.47 5391.34,3962.65 5377.53,3962.65 5363.72,3976.47 5349.9,3962.65 5336.09,3962.65 ; 5347.14,2979.14 5380.29,2979.14 5380.29,3012.3 5347.14,3012.3 5347.14,2979.14
  lines w12: 5286,2806.48 8517.49,2806.48 ; 5286,4049.68 8517.49,4049.68 ; 5623.86,2682.16 5623.86,4174 ; 5955.86,2682.16 5955.86,4174 ; 6592.43,2682.16 6592.43,4174 ; 6851.57,2682.16 6851.57,4174 ; 7226.72,2682.16 7226.72,4174 ; 7951.05,2682.16 7951.05,4174 ; 5286,2682.16 8517.49,2682.16 8517.49,4174 5286,4174 5286,2682.16
  text "Symbol" at 5360.59,4086.97 h72
  text "Quantity" at 5661.16,4086.97 h72
  text "Finished Hole Size" at 5993.16,4086.97 h72
  text "Plated" at 6629.72,4086.97 h72
  text "Hole Type" at 6888.86,4086.97 h72
  text "Drill Layer Pair" at 7264.02,4086.97 h72
  text "Hole Tolerance" at 7988.35,4086.97 h72
  text "258" at 5661.16,3962.65 h60
  text "7.87mil (0.200mm)" at 5993.16,3962.65 h60
  text "PTH" at 6629.72,3962.65 h60
  text "Round" at 6888.86,3962.65 h60
  text "Top Layer - Bottom Layer" at 7264.02,3962.65 h60
  text "759" at 5661.16,3838.33 h60
  text "10.00mil (0.254mm)" at 5993.16,3838.33 h60
  text "PTH" at 6629.72,3838.33 h60
  text "Round" at 6888.86,3838.33 h60
  text "Top Layer - Bottom Layer" at 7264.02,3838.33 h60
  text "3" at 5661.16,3714.01 h60
  text "27.56mil (0.700mm)" at 5993.16,3714.01 h60
  text "PTH" at 6629.72,3714.01 h60
  text "Round" at 6888.86,3714.01 h60
  text "Top Layer - Bottom Layer" at 7264.02,3714.01 h60
  text "16" at 5661.16,3589.69 h60
  text "33.47mil (0.850mm)" at 5993.16,3589.69 h60
  text "PTH" at 6629.72,3589.69 h60
  text "Round" at 6888.86,3589.69 h60
  text "Top Layer - Bottom Layer" at 7264.02,3589.69 h60
  text "39" at 5661.16,3465.37 h60
  text "40.00mil (1.016mm)" at 5993.16,3465.37 h60
  text "PTH" at 6629.72,3465.37 h60
  text "Round" at 6888.86,3465.37 h60
  text "Top Layer - Bottom Layer" at 7264.02,3465.37 h60
  text "46" at 5661.16,3341.05 h60
  text "40.16mil (1.020mm)" at 5993.16,3341.05 h60
  text "PTH" at 6629.72,3341.05 h60
  text "Round" at 6888.86,3341.05 h60
  text "Top Layer - Bottom Layer" at 7264.02,3341.05 h60
  text "5" at 5661.16,3216.73 h60
  text "47.24mil (1.200mm)" at 5993.16,3216.73 h60
  text "PTH" at 6629.72,3216.73 h60
  text "Round" at 6888.86,3216.73 h60
  text "Top Layer - Bottom Layer" at 7264.02,3216.73 h60
  text "6" at 5661.16,3092.41 h60
  text "51.18mil (1.300mm)" at 5993.16,3092.41 h60
  text "PTH" at 6629.72,3092.41 h60
  text "Round" at 6888.86,3092.41 h60
  text "Top Layer - Bottom Layer" at 7264.02,3092.41 h60
  text "5" at 5661.16,2968.09 h60
  text "51.18mil (1.300mm)" at 5993.16,2968.09 h60
  text "PTH" at 6629.72,2968.09 h60
  text "Round" at 6888.86,2968.09 h60
  text "Top Layer - Bottom Layer" at 7264.02,2968.09 h60
  text "+/-3.94mil" at 7988.35,2968.09 h60
  text "4" at 5661.16,2843.77 h60
  text "125.98mil (3.200mm)" at 5993.16,2843.77 h60
  text "PTH" at 6629.72,2843.77 h60
  text "Round" at 6888.86,2843.77 h60
  text "Top Layer - Bottom Layer" at 7264.02,2843.77 h60
  text "1141 Total" at 5661.16,2719.45 h60
  text ".Layer_Name" at 577,-428.49 h60
M17 Embedded Cavity:
  text ".Layer_Name" at 577,-428.49 h60
M18 Embedded Assembly:
  text ".Layer_Name" at 577,-428.49 h60
M19 Embedded Keepout:
  text ".Layer_Name" at 577,-428.49 h60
